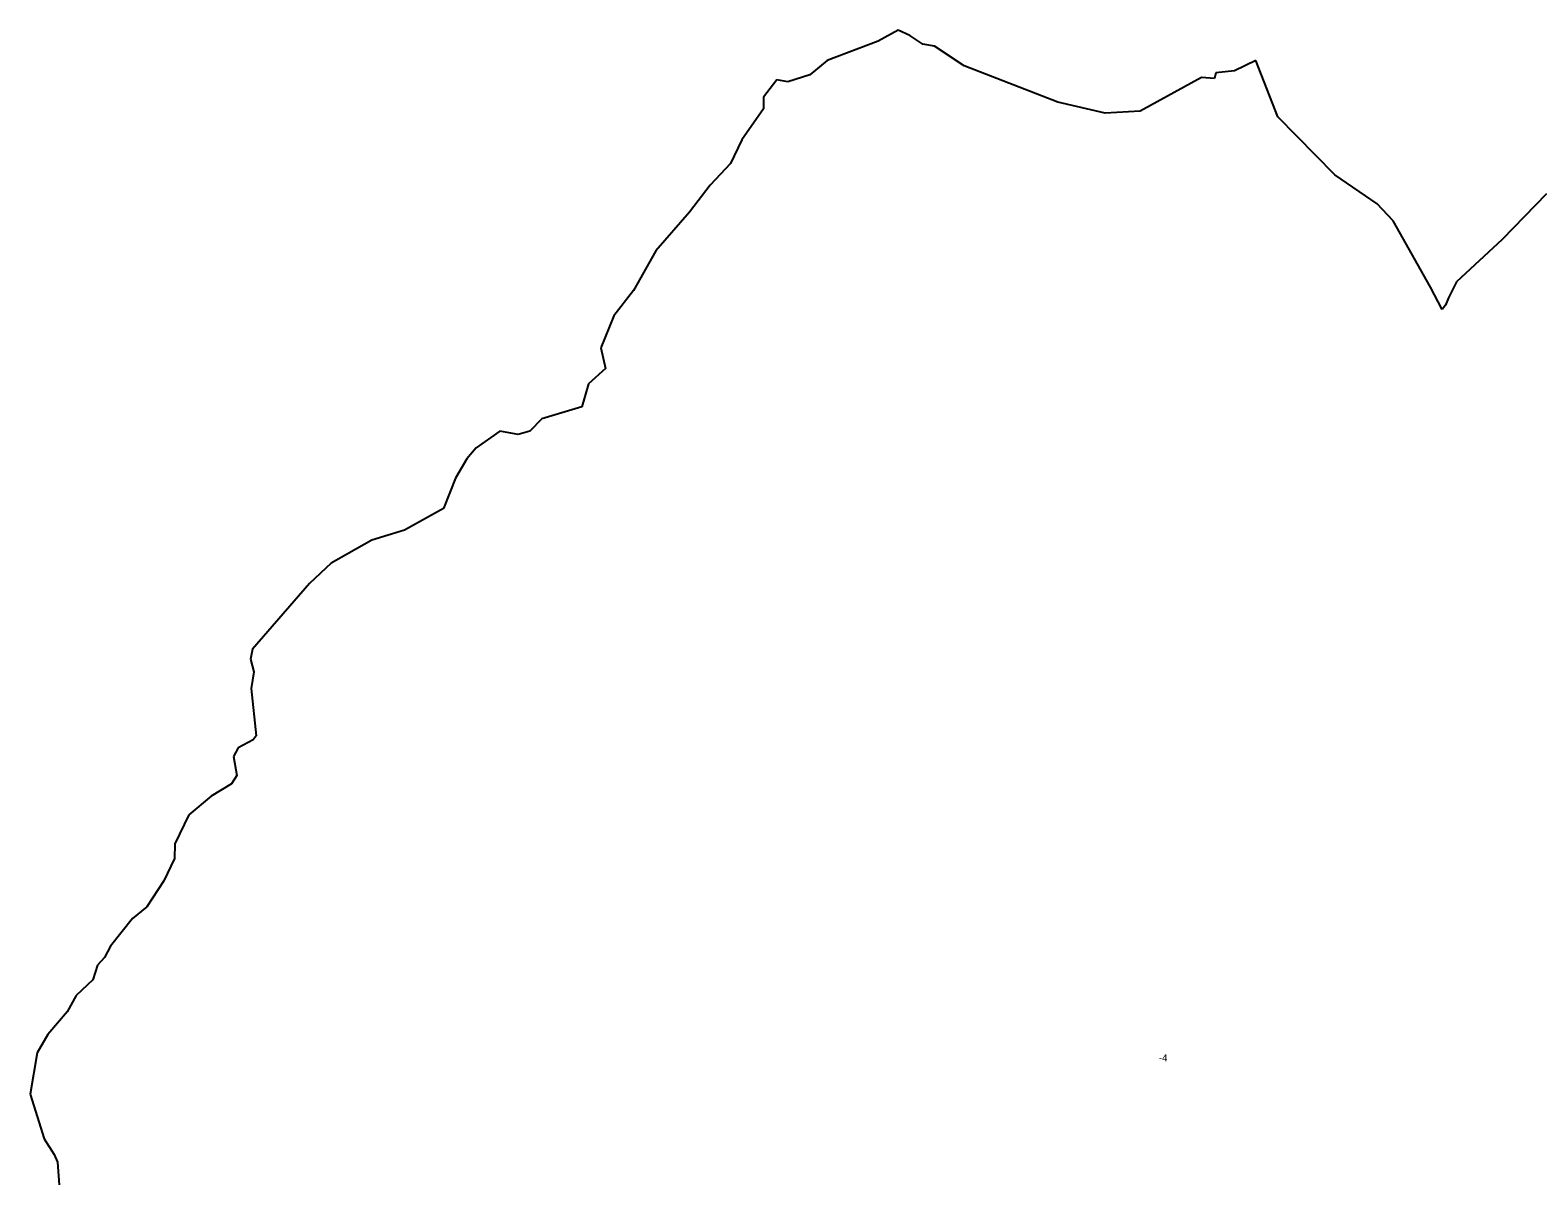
# Model space of a CAD drawing. Extents: x -790709 to -785360, y -974907 to -970918.
# Drawn here: x -790709 to -788603, y -972522 to -970921 of the extents above; entities that cross this region are included whole.
import ezdxf

# ---------------------------------------------------------------- set-up
doc = ezdxf.new("R2010")
doc.units = 0
doc.layers.add('Vrstva 13', color=7, linetype='Continuous')
doc.layers.add('Vrstva 15', color=7, linetype='Continuous')

msp = doc.modelspace()

# ---------------------------------------------------------------- linework, layer by layer
at = {"layer": 'Vrstva 13'}
for p, q in [((-789496.6, -970921.5), (-789524.6, -970937)), ((-789480, -970928.7), (-789496.6, -970921.5)), ((-789524.6, -970937), (-789595.7, -970964)), ((-789461.8, -970941.2), (-789480, -970928.7)), ((-789445.7, -970943.8), (-789461.8, -970941.2)), ((-789404.2, -970971.3), (-789445.7, -970943.8)), ((-788996.9, -970963.8), (-789026.5, -970978.3)), ((-788966.1, -971042.7), (-788996.9, -970963.8)), ((-789620.1, -970983.8), (-789650.7, -970993.6)), ((-789595.7, -970964), (-789620.1, -970983.8)), ((-789273.5, -971022.2), (-789404.2, -970971.3)), ((-789052.7, -970980.9), (-789054.5, -970988.9)), ((-789026.5, -970978.3), (-789052.7, -970980.9)), ((-789666.2, -970991), (-789684.7, -971014.9)), ((-789650.7, -970993.6), (-789666.2, -970991)), ((-789072.7, -970987.4), (-789158.3, -971034.6)), ((-789054.5, -970988.9), (-789072.7, -970987.4)), ((-789684.7, -971014.9), (-789684.7, -971031.5)), ((-789207.1, -971037.2), (-789273.5, -971022.2)), ((-789684.7, -971031.5), (-789715, -971074.8)), ((-789158.3, -971034.6), (-789207.1, -971037.2)), ((-788886.2, -971123.6), (-788966.1, -971042.7)), ((-789715, -971074.8), (-789730.6, -971107.5)), ((-789730.6, -971107.5), (-789759.1, -971138.2)), ((-788827, -971164.1), (-788886.2, -971123.6)), ((-789759.1, -971138.2), (-789787.9, -971175.5)), ((-788590.7, -971150.1), (-788652.5, -971213.7)), ((-788805, -971188), (-788827, -971164.1)), ((-789787.9, -971175.5), (-789834.9, -971229.5)), ((-788752.6, -971280.4), (-788805, -971188)), ((-788652.5, -971213.7), (-788716.3, -971272.8)), ((-789834.9, -971229.5), (-789866.2, -971285.1)), ((-788716.3, -971272.8), (-788727.4, -971295.2)), ((-789866.2, -971285.1), (-789893.8, -971320.3)), ((-788736.2, -971311.8), (-788752.6, -971280.4)), ((-788727.4, -971295.2), (-788731.6, -971305.8)), ((-789893.8, -971320.3), (-789911.9, -971365)), ((-788731.6, -971305.8), (-788736.2, -971311.8)), ((-789911.9, -971365), (-789905.2, -971394.1)), ((-789905.2, -971394.1), (-789929.3, -971415.3)), ((-789929.3, -971415.3), (-789938.6, -971447.5)), ((-789938.6, -971447.5), (-789994.4, -971464.4)), ((-789994.4, -971464.4), (-790011, -971481.8)), ((-790053, -971481.5), (-790086.2, -971505.1)), ((-790027.6, -971486.4), (-790053, -971481.5)), ((-790011, -971481.8), (-790027.6, -971486.4)), ((-790086.2, -971505.1), (-790099.2, -971520.2)), ((-790099.2, -971520.2), (-790114.8, -971547.4)), ((-790114.8, -971547.4), (-790131.9, -971589.7)), ((-790131.9, -971589.7), (-790186.1, -971619.8)), ((-790231.8, -971633.8), (-790288.6, -971665.8)), ((-790186.1, -971619.8), (-790231.8, -971633.8)), ((-790288.6, -971665.8), (-790319, -971694.3)), ((-790319, -971694.3), (-790398.8, -971785.9)), ((-790398.8, -971785.9), (-790401.4, -971800.2)), ((-790401.4, -971800.2), (-790396.8, -971817.8)), ((-790396.8, -971817.8), (-790400.7, -971840.9)), ((-790400.7, -971840.9), (-790393.4, -971907.1)), ((-790393.4, -971907.1), (-790397.6, -971912.6)), ((-790418.8, -971924), (-790425.1, -971936.2)), ((-790397.6, -971912.6), (-790418.8, -971924)), ((-790425.1, -971936.2), (-790420.4, -971962.4)), ((-790428.2, -971974.3), (-790456.4, -971991.5)), ((-790420.4, -971962.4), (-790428.2, -971974.3)), ((-790456.4, -971991.5), (-790487.6, -972017.7)), ((-790487.6, -972017.7), (-790507, -972058.2)), ((-790507, -972058.2), (-790507.8, -972078.7)), ((-790507.8, -972078.7), (-790522.6, -972109.5)), ((-790522.6, -972109.5), (-790546.2, -972145.9)), ((-790566.2, -972162.2), (-790597.1, -972200.9)), ((-790546.2, -972145.9), (-790566.2, -972162.2)), ((-790597.1, -972200.9), (-790605.6, -972217)), ((-790615.2, -972227.6), (-790622, -972247.9)), ((-790605.6, -972217), (-790615.2, -972227.6)), ((-790622, -972247.9), (-790645.3, -972269.9)), ((-790645.3, -972269.9), (-790657.5, -972292.5)), ((-790657.5, -972292.5), (-790684.7, -972324.4)), ((-790684.7, -972324.4), (-790699.8, -972349.9)), ((-790699.8, -972349.9), (-790709.4, -972407.5)), ((-790709.4, -972407.5), (-790689.9, -972470.3)), ((-790689.9, -972470.3), (-790675.7, -972491.8)), ((-790675.7, -972491.8), (-790671.2, -972502.7)), ((-790671.2, -972502.7), (-790668.4, -972540.9))]:
    msp.add_line(p, q, dxfattribs=at)

# ---------------------------------------------------------------- texts
at = {"layer": 'Vrstva 15'}
msp.add_text('-4', height=10, dxfattribs=at).set_placement((-789132.1, -972361.9))

doc.saveas('drawing.dxf')
